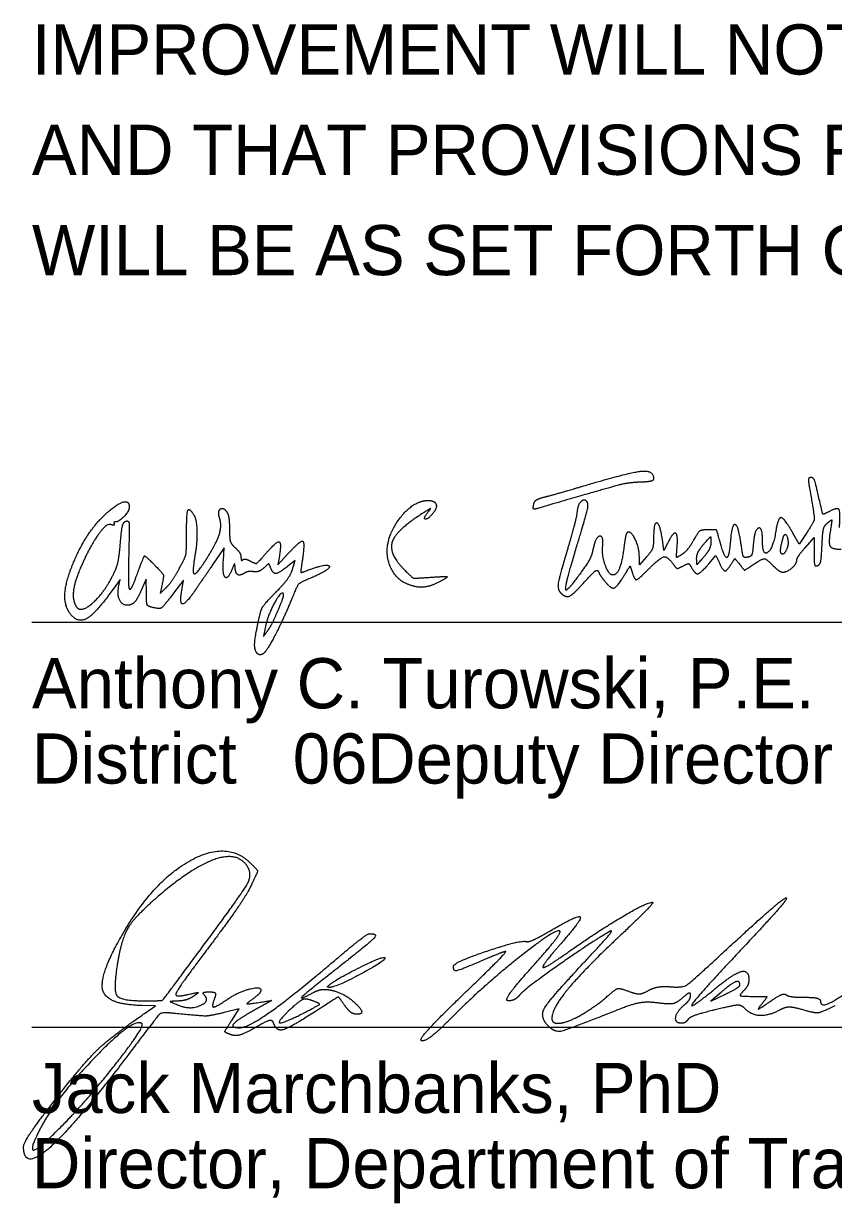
# Model space of a CAD drawing. Extents: x 0 to 34, y 0 to 22.
# Drawn here: x 24.504 to 26.766, y 7.305 to 10.597 of the extents above; entities that cross this region are included whole.
import ezdxf

# ---------------------------------------------------------------- set-up
doc = ezdxf.new("R2010")
doc.units = 0
doc.layers.add('GM_X_Minor_Lake', color=7, linetype='Continuous')
doc.layers.add('GM_X_Minor_Lake_Text', color=7, linetype='Continuous')

msp = doc.modelspace()

# ---------------------------------------------------------------- linework, layer by layer
at = {"layer": 'GM_X_Minor_Lake'}
for p, q in [((25.9287, 9.2547), (25.9287, 9.2547)), ((25.5689, 9.0363), (25.5689, 9.0363)), ((25.2156, 8.9606), (25.2156, 8.9606)), ((25.157, 8.8395), (25.157, 8.8395)), ((24.9902, 8.0019), (24.9902, 8.0019)), ((25.3555, 7.912), (25.3555, 7.912)), ((26.5045, 7.914), (26.5045, 7.914)), ((25.3107, 7.8703), (25.3107, 7.8703)), ((25.7273, 7.883), (25.7273, 7.883))]:
    msp.add_line(p, q, dxfattribs=at)
for points in [[(26.3033, 9.1485), (26.2923, 9.1263), (26.2879, 9.1577)], [(26.6905, 9.1753), (26.6698, 9.1442), (26.6524, 9.1752)], [(26.6875, 9.1355), (26.7115, 9.1629), (26.7115, 9.1219)], [(25.0623, 9.0989), (25.0648, 9.1343), (25.032, 9.0863)], [(25.2187, 9.112), (25.2144, 9.0863), (25.2425, 9.1171)], [(25.2556, 9.0747), (25.2625, 9.0987), (25.2419, 9.0825)], [(26.2437, 9.1088), (26.224, 9.0863), (26.2237, 9.1087)], [(26.4178, 9.0897), (26.4375, 9.1131), (26.4463, 9.0937)], [(24.7697, 9.0239), (24.774, 9.046), (24.757, 9.0221)], [(24.8473, 9.0092), (24.8471, 9.0463), (24.8322, 9.0135)], [(24.8914, 9.0326), (24.8859, 9.0063), (24.902, 9.0223)], [(24.946, 9.0149), (24.9507, 9.0436), (24.9233, 9.0077)], [(26.4527, 7.8943), (26.4232, 7.8687), (26.4638, 7.8884)], [(24.8425, 7.8349), (24.8732, 7.8561), (24.8354, 7.8568)], [(25.0855, 7.8151), (25.1067, 7.8474), (25.0649, 7.8373)]]:
    msp.add_lwpolyline(points, dxfattribs=at)
for points in [[(26.0677, 9.3068), (26.1931, 9.3442), (26.2635, 9.3515), (26.2635, 9.3274)], [(26.2635, 9.3274), (26.2635, 9.322), (26.2477, 9.3178), (26.2253, 9.3172)], [(26.7022, 9.3303), (26.6963, 9.3303), (26.6954, 9.3192), (26.6995, 9.2963)], [(26.7309, 9.2481), (26.7165, 9.3119), (26.7101, 9.3303), (26.7022, 9.3303)], [(26.2253, 9.3172), (26.1933, 9.3162), (26.1405, 9.3027), (25.9407, 9.2443)], [(25.9595, 9.2761), (25.9749, 9.2799), (26.0236, 9.2937), (26.0677, 9.3068)], [(26.6995, 9.2963), (26.7128, 9.2214), (26.7117, 9.2075), (26.6905, 9.1753)], [(24.7437, 9.2372), (24.7705, 9.2598), (24.7995, 9.2652), (24.7995, 9.2475)], [(25.5197, 9.124), (25.5201, 9.173), (25.5945, 9.2663), (25.6332, 9.2663)], [(25.6332, 9.2663), (25.6521, 9.2663), (25.6602, 9.2457), (25.6474, 9.2302)], [(25.9407, 9.2443), (25.9295, 9.2411), (25.9266, 9.2437), (25.9287, 9.2547)], [(25.9287, 9.2547), (25.9304, 9.2637), (25.9422, 9.2719), (25.9595, 9.2761)], [(26.039, 9.1045), (26.0736, 9.22), (26.0827, 9.2577), (26.0773, 9.2632)], [(26.0773, 9.2632), (26.0685, 9.2719), (26.0512, 9.2529), (26.0495, 9.2327)], [(24.6396, 9.0826), (24.6598, 9.1339), (24.7107, 9.2095), (24.7437, 9.2372)], [(24.7995, 9.2475), (24.7995, 9.2369), (24.7707, 9.2063), (24.7606, 9.2063)], [(24.9595, 9.1738), (24.9595, 9.2298), (24.9665, 9.2473), (24.9801, 9.2254)], [(24.9801, 9.2254), (24.9876, 9.2132), (24.9892, 9.1489), (24.983, 9.1129)], [(25.0516, 9.218), (25.0458, 9.2363), (25.0625, 9.2487), (25.0723, 9.2333)], [(25.0723, 9.2333), (25.0761, 9.2273), (25.0793, 9.2058), (25.0794, 9.1855)], [(25.6195, 9.2309), (25.5442, 9.1833), (25.5228, 9.1178), (25.5678, 9.0728)], [(25.6325, 9.2322), (25.6421, 9.2443), (25.6405, 9.2441), (25.6195, 9.2309)], [(25.6474, 9.2302), (25.6335, 9.2134), (25.6192, 9.2153), (25.6325, 9.2322)], [(26.0495, 9.2327), (26.0487, 9.2224), (26.0371, 9.1773), (26.0237, 9.1324)], [(26.7525, 9.2349), (26.7378, 9.227), (26.7353, 9.2285), (26.7309, 9.2481)], [(26.7823, 9.1906), (26.7857, 9.2343), (26.7766, 9.2478), (26.7525, 9.2349)], [(24.7485, 9.199), (24.7359, 9.2039), (24.6881, 9.1356), (24.6629, 9.077)], [(24.7574, 9.2006), (24.7584, 9.1975), (24.7544, 9.1968), (24.7485, 9.199)], [(24.7606, 9.2063), (24.7578, 9.2063), (24.7563, 9.2037), (24.7574, 9.2006)], [(24.775, 9.1497), (24.7778, 9.1849), (24.7833, 9.2063), (24.79, 9.2085)], [(24.79, 9.2085), (24.7983, 9.2113), (24.7999, 9.1922), (24.798, 9.1151)], [(25.015, 9.1028), (25.0431, 9.1472), (25.0586, 9.1959), (25.0516, 9.218)], [(26.2879, 9.1577), (26.2818, 9.2012), (26.2635, 9.2055), (26.2635, 9.1634)], [(26.5075, 9.1459), (26.5005, 9.1969), (26.4815, 9.2014), (26.4779, 9.1529)], [(26.5675, 9.1543), (26.5675, 9.1937), (26.5449, 9.1849), (26.5419, 9.1444)], [(26.6524, 9.1752), (26.629, 9.217), (26.6111, 9.2196), (26.605, 9.182)], [(26.7338, 9.1403), (26.7355, 9.1769), (26.7401, 9.1962), (26.7492, 9.2036)], [(26.7492, 9.2036), (26.7609, 9.2133), (26.7616, 9.2112), (26.7571, 9.1828)], [(24.9388, 9.0758), (24.9559, 9.1069), (24.9595, 9.1239), (24.9595, 9.1738)], [(25.0794, 9.1855), (25.0795, 9.1591), (25.084, 9.1447), (25.0955, 9.1343)], [(26.1212, 9.1366), (26.1245, 9.1685), (26.1015, 9.1648), (26.0949, 9.1325)], [(26.1924, 9.1783), (26.1887, 9.1783), (26.1837, 9.161), (26.1812, 9.1399)], [(26.2237, 9.1087), (26.2235, 9.1331), (26.2031, 9.1783), (26.1924, 9.1783)], [(26.2635, 9.1634), (26.2635, 9.1406), (26.2578, 9.1247), (26.2437, 9.1088)], [(26.3291, 9.1352), (26.332, 9.1713), (26.3181, 9.1785), (26.3033, 9.1485)], [(26.3747, 9.1546), (26.3657, 9.1386), (26.3512, 9.121), (26.3425, 9.1155)], [(26.4155, 9.1846), (26.3961, 9.184), (26.3878, 9.1779), (26.3747, 9.1546)], [(26.4032, 9.1439), (26.4221, 9.1653), (26.423, 9.1655), (26.4232, 9.1488)], [(26.4493, 9.1497), (26.4407, 9.1822), (26.4377, 9.1852), (26.4155, 9.1846)], [(26.605, 9.182), (26.5969, 9.1323), (26.5675, 9.1106), (26.5675, 9.1543)], [(26.6205, 9.1443), (26.6234, 9.1564), (26.6269, 9.1677), (26.6284, 9.1695)], [(26.6284, 9.1695), (26.634, 9.176), (26.641, 9.1458), (26.6366, 9.1343)], [(26.7571, 9.1828), (26.7513, 9.1467), (26.7608, 9.1303), (26.7876, 9.1303)], [(24.7618, 9.0743), (24.7666, 9.0853), (24.7725, 9.1192), (24.775, 9.1497)], [(25.0955, 9.1343), (25.1043, 9.1263), (25.1115, 9.1144), (25.1115, 9.1077)], [(25.1806, 9.1179), (25.2101, 9.152), (25.225, 9.1496), (25.2187, 9.112)], [(25.2425, 9.1171), (25.2773, 9.1553), (25.2902, 9.1499), (25.2828, 9.1003)], [(25.5689, 9.0363), (25.5476, 9.0466), (25.5194, 9.0968), (25.5197, 9.124)], [(26.0237, 9.1324), (25.9997, 9.0514), (25.9946, 9.0179), (26.0048, 9.0076)], [(26.0949, 9.1325), (26.092, 9.1183), (26.0839, 9.0985), (26.0769, 9.0885)], [(26.1498, 9.0583), (26.1386, 9.0583), (26.1187, 9.1127), (26.1212, 9.1366)], [(26.1812, 9.1399), (26.1762, 9.0979), (26.161, 9.0583), (26.1498, 9.0583)], [(26.3425, 9.1155), (26.3277, 9.1063), (26.3269, 9.1076), (26.3291, 9.1352)], [(26.3837, 9.1039), (26.3836, 9.1135), (26.3924, 9.1315), (26.4032, 9.1439)], [(26.4232, 9.1488), (26.4234, 9.1391), (26.4146, 9.1211), (26.4037, 9.1088)], [(26.4779, 9.1529), (26.4746, 9.1078), (26.461, 9.1063), (26.4493, 9.1497)], [(26.5263, 9.1079), (26.516, 9.106), (26.5119, 9.1143), (26.5075, 9.1459)], [(26.5419, 9.1444), (26.5402, 9.1205), (26.5356, 9.1097), (26.5263, 9.1079)], [(26.6366, 9.1343), (26.6283, 9.1127), (26.6149, 9.1211), (26.6205, 9.1443)], [(26.6635, 9.1005), (26.6635, 9.1047), (26.6743, 9.1205), (26.6875, 9.1355)], [(26.7115, 9.1219), (26.7115, 9.0927), (26.7144, 9.0819), (26.7215, 9.0843)], [(26.7215, 9.0843), (26.7278, 9.0864), (26.7324, 9.107), (26.7338, 9.1403)], [(24.798, 9.1151), (24.7966, 9.0619), (24.7979, 9.0183), (24.8008, 9.0183)], [(24.8201, 9.0563), (24.8401, 9.1107), (24.8441, 9.1128), (24.8721, 9.0841)], [(24.983, 9.1129), (24.9743, 9.0633), (24.9874, 9.0592), (25.015, 9.1028)], [(25.087, 9.0756), (25.0747, 9.045), (25.0596, 9.0592), (25.0623, 9.0989)], [(25.095, 9.0808), (25.0946, 9.0903), (25.0922, 9.0887), (25.087, 9.0756)], [(25.1115, 9.1077), (25.1115, 9.1011), (25.1138, 9.0979), (25.1165, 9.1007)], [(25.1165, 9.1007), (25.1193, 9.1035), (25.1291, 9.1017), (25.1382, 9.0969)], [(25.1382, 9.0969), (25.1526, 9.0892), (25.1582, 9.092), (25.1806, 9.1179)], [(25.1942, 9.0787), (25.19, 9.0897), (25.188, 9.0896), (25.1752, 9.078)], [(25.2828, 9.1003), (25.2779, 9.0678), (25.2788, 9.0643), (25.2911, 9.0691)], [(26.0769, 9.0885), (26.0249, 9.0138), (26.0132, 9.0187), (26.039, 9.1045)], [(26.2518, 9.077), (26.2818, 9.107), (26.3025, 9.1108), (26.318, 9.089)], [(26.318, 9.089), (26.3265, 9.077), (26.3315, 9.0759), (26.3451, 9.0832)], [(26.3451, 9.0832), (26.3585, 9.0904), (26.3633, 9.0896), (26.3691, 9.0792)], [(26.3691, 9.0792), (26.3798, 9.06), (26.3957, 9.0635), (26.4178, 9.0897)], [(26.4037, 9.1088), (26.3849, 9.0873), (26.384, 9.0871), (26.3837, 9.1039)], [(26.4463, 9.0937), (26.4569, 9.0704), (26.4681, 9.069), (26.4808, 9.0895)], [(26.4808, 9.0895), (26.49, 9.1042), (26.4907, 9.1042), (26.5039, 9.0879)], [(26.5039, 9.0879), (26.5173, 9.0712), (26.5176, 9.0712), (26.5405, 9.0865)], [(26.5405, 9.0865), (26.5671, 9.1042), (26.5784, 9.1034), (26.5999, 9.0819)], [(26.6249, 9.0663), (26.6366, 9.0663), (26.6635, 9.0901), (26.6635, 9.1005)], [(24.6342, 8.9507), (24.6185, 8.9722), (24.6211, 9.0357), (24.6396, 9.0826)], [(24.6629, 9.077), (24.6464, 9.0385), (24.6408, 8.9877), (24.6511, 8.9709)], [(24.6511, 8.9709), (24.6644, 8.9494), (24.7369, 9.0172), (24.7618, 9.0743)], [(24.8008, 9.0183), (24.8038, 9.0183), (24.8125, 9.0354), (24.8201, 9.0563)], [(24.8721, 9.0841), (24.8933, 9.0625), (24.8961, 9.055), (24.8914, 9.0326)], [(24.902, 9.0223), (24.9109, 9.0311), (24.9275, 9.0552), (24.9388, 9.0758)], [(25.032, 9.0863), (25.0139, 9.0599), (24.9911, 9.0267), (24.9813, 9.0126)], [(25.1215, 9.0636), (25.1084, 9.0554), (25.0956, 9.0637), (25.095, 9.0808)], [(25.1462, 9.0675), (25.1381, 9.0688), (25.127, 9.0671), (25.1215, 9.0636)], [(25.1752, 9.078), (25.1673, 9.0709), (25.1542, 9.0662), (25.1462, 9.0675)], [(25.2419, 9.0825), (25.2173, 9.0632), (25.2007, 9.0618), (25.1942, 9.0787)], [(25.2086, 9.0099), (25.2307, 9.0323), (25.2518, 9.0614), (25.2556, 9.0747)], [(25.2911, 9.0691), (25.3506, 9.0919), (25.365, 9.0749), (25.3071, 9.0501)], [(25.5678, 9.0728), (25.5906, 9.05), (25.5952, 9.0487), (25.6398, 9.0519)], [(26.0719, 9.0403), (26.0918, 9.0626), (26.1072, 9.0742), (26.1092, 9.0684)], [(26.1092, 9.0684), (26.1112, 9.063), (26.1191, 9.0507), (26.1269, 9.0411)], [(26.1269, 9.0411), (26.1444, 9.0194), (26.1621, 9.025), (26.1826, 9.0588)], [(26.1826, 9.0588), (26.197, 9.0824), (26.1982, 9.0829), (26.2032, 9.0671)], [(26.2032, 9.0671), (26.2106, 9.0439), (26.2208, 9.046), (26.2518, 9.077)], [(26.5999, 9.0819), (26.6085, 9.0733), (26.6197, 9.0663), (26.6249, 9.0663)], [(24.757, 9.0221), (24.7073, 8.9523), (24.6552, 8.922), (24.6342, 8.9507)], [(24.8052, 8.9761), (24.7863, 8.9688), (24.7648, 8.9979), (24.7697, 9.0239)], [(25.3071, 9.0501), (25.2757, 9.0367), (25.2684, 9.0288), (25.2535, 8.9924)], [(25.6639, 9.0385), (25.6366, 9.0244), (25.5956, 9.0235), (25.5689, 9.0363)], [(25.6398, 9.0519), (25.666, 9.0538), (25.6875, 9.0543), (25.6875, 9.053)], [(25.6875, 9.053), (25.6875, 9.0518), (25.6769, 9.0452), (25.6639, 9.0385)], [(26.0048, 9.0076), (26.0182, 8.9943), (26.0408, 9.0053), (26.0719, 9.0403)], [(24.8322, 9.0135), (24.8241, 8.9955), (24.8119, 8.9786), (24.8052, 8.9761)], [(24.8615, 8.9685), (24.8507, 8.9713), (24.8474, 8.9807), (24.8473, 9.0092)], [(24.9233, 9.0077), (24.894, 8.9694), (24.8837, 8.9628), (24.8615, 8.9685)], [(24.9813, 9.0126), (24.9565, 8.9769), (24.94, 8.9779), (24.946, 9.0149)], [(25.16, 8.9294), (25.1667, 8.9606), (25.1773, 8.9781), (25.2086, 9.0099)], [(25.2535, 8.9924), (25.2283, 8.9307), (25.1799, 8.8398), (25.1705, 8.8367)], [(25.2295, 9.0069), (25.2229, 9.0136), (25.1859, 8.9448), (25.1798, 8.9143)], [(25.2156, 8.9606), (25.2255, 8.9838), (25.2318, 9.0046), (25.2295, 9.0069)], [(25.1858, 8.9023), (25.1922, 8.9111), (25.2056, 8.9373), (25.2156, 8.9606)], [(25.157, 8.8395), (25.149, 8.8475), (25.1502, 8.8837), (25.16, 8.9294)], [(25.1798, 8.9143), (25.1745, 8.8884), (25.175, 8.8875), (25.1858, 8.9023)], [(25.1705, 8.8367), (25.1661, 8.8352), (25.16, 8.8364), (25.157, 8.8395)], [(24.7789, 8.0526), (24.8651, 8.203), (25.0732, 8.319), (25.1389, 8.2534)], [(25.1299, 8.2442), (25.104, 8.2862), (24.9779, 8.245), (24.8825, 8.1634)], [(24.9902, 8.0019), (25.1115, 8.1653), (25.144, 8.2215), (25.1299, 8.2442)], [(25.1389, 8.2534), (25.1577, 8.2346), (25.1577, 8.2295), (25.1394, 8.1911)], [(25.1394, 8.1911), (25.1284, 8.1681), (25.0767, 8.0926), (25.0245, 8.0232)], [(24.8825, 8.1634), (24.8159, 8.1064), (24.7771, 8.0423), (24.766, 7.971)], [(26.0326, 8.0111), (26.1131, 8.0677), (26.2445, 8.1449), (26.2602, 8.1449)], [(26.2602, 8.1449), (26.265, 8.1449), (26.2237, 8.1023), (26.1684, 8.0502)], [(26.4869, 8.0315), (26.5619, 8.1006), (26.6279, 8.1572), (26.6336, 8.1573)], [(26.6336, 8.1573), (26.6394, 8.1574), (26.5873, 8.0972), (26.518, 8.0236)], [(25.9736, 8.0646), (26.0524, 8.1108), (26.0646, 8.0975), (26.0054, 8.0302)], [(24.8354, 7.8568), (24.7375, 7.8585), (24.7141, 7.9396), (24.7789, 8.0526)], [(25.369, 7.9791), (25.4194, 8.022), (25.4649, 8.0571), (25.4701, 8.0573)], [(25.4701, 8.0573), (25.495, 8.0578), (25.4716, 8.0322), (25.3857, 7.9649)], [(25.7047, 7.9668), (25.7049, 7.9774), (25.8923, 8.0405), (25.908, 8.0354)], [(26.0017, 8.0644), (25.9921, 8.074), (25.7824, 7.907), (25.7045, 7.8278)], [(26.142, 8.0639), (26.0929, 8.0361), (25.9046, 7.9039), (25.8914, 7.888)], [(25.908, 8.0354), (25.9136, 8.0335), (25.9431, 8.0467), (25.9736, 8.0646)], [(25.9239, 7.964), (25.9702, 8.0157), (26.0052, 8.0609), (26.0017, 8.0644)], [(26.1684, 8.0502), (26.0687, 7.9565), (25.9795, 7.8484), (25.9795, 7.8214)], [(26.0768, 7.985), (26.123, 8.0342), (26.1523, 8.0697), (26.142, 8.0639)], [(24.844, 7.8699), (24.8907, 7.8699), (24.8953, 7.874), (24.9902, 8.0019)], [(25.0245, 8.0232), (24.9722, 7.9539), (24.9295, 7.8932), (24.9295, 7.8884)], [(25.7273, 7.883), (25.7983, 7.9514), (25.8537, 8.0074), (25.8502, 8.0074)], [(25.8502, 8.0074), (25.8468, 8.0074), (25.8178, 7.9962), (25.7857, 7.9824)], [(26.0054, 8.0302), (25.9774, 7.9984), (25.9545, 7.9687), (25.9545, 7.9643)], [(25.9545, 7.9643), (25.9545, 7.9598), (25.9896, 7.9809), (26.0326, 8.0111)], [(26.3119, 7.9091), (26.3453, 7.9063), (26.3688, 7.9227), (26.4869, 8.0315)], [(26.518, 8.0236), (26.3885, 7.8861), (26.3564, 7.8388), (26.4386, 7.9065)], [(24.766, 7.971), (24.7545, 7.8977), (24.776, 7.8699), (24.844, 7.8699)], [(25.1076, 7.7949), (25.1307, 7.7949), (25.2567, 7.8837), (25.369, 7.9791)], [(25.3555, 7.912), (25.3759, 7.9299), (25.5079, 7.9956), (25.5131, 7.9905)], [(25.5131, 7.9905), (25.5193, 7.9843), (25.3767, 7.9074), (25.359, 7.9074)], [(25.7857, 7.9824), (25.7231, 7.9556), (25.7044, 7.952), (25.7047, 7.9668)], [(25.9697, 7.7993), (25.9445, 7.8246), (25.9734, 7.8747), (26.0768, 7.985)], [(26.7295, 7.8684), (26.7295, 7.8456), (26.8248, 7.907), (26.8951, 7.9753)], [(25.3857, 7.9649), (25.2925, 7.8919), (25.271, 7.8704), (25.315, 7.8939)], [(25.8581, 7.8699), (25.8478, 7.8699), (25.8767, 7.9112), (25.9239, 7.964)], [(26.4386, 7.9065), (26.487, 7.9464), (26.5295, 7.9568), (26.5295, 7.9287)], [(25.0736, 7.8743), (25.1025, 7.8941), (25.167, 7.9116), (25.167, 7.8997)], [(25.359, 7.9074), (25.3542, 7.9074), (25.3526, 7.9095), (25.3555, 7.912)], [(26.137, 7.885), (26.1573, 7.903), (26.1701, 7.9056), (26.1939, 7.8966)], [(26.2489, 7.8987), (26.2623, 7.9062), (26.2906, 7.9109), (26.3119, 7.9091)], [(26.5045, 7.914), (26.5045, 7.9275), (26.4804, 7.9183), (26.4527, 7.8943)], [(26.4638, 7.8884), (26.4862, 7.8992), (26.5045, 7.9107), (26.5045, 7.914)], [(26.5295, 7.9287), (26.5295, 7.9198), (26.5227, 7.9057), (26.5145, 7.8974)], [(24.9357, 7.8693), (24.9133, 7.8685), (24.9138, 7.8671), (24.9399, 7.8567)], [(24.9295, 7.8884), (24.9295, 7.8836), (24.9449, 7.8833), (24.9638, 7.8877)], [(24.9795, 7.883), (24.9692, 7.876), (24.9495, 7.8699), (24.9357, 7.8693)], [(24.9399, 7.8567), (24.9698, 7.8447), (25.026, 7.8693), (25.0086, 7.8867)], [(24.9638, 7.8877), (24.9894, 7.8936), (24.9934, 7.8924), (24.9795, 7.883)], [(25.0086, 7.8867), (25.004, 7.8912), (25.0103, 7.8949), (25.0225, 7.8949)], [(25.0225, 7.8949), (25.037, 7.8949), (25.0422, 7.8885), (25.0375, 7.8762)], [(25.0375, 7.8762), (25.0285, 7.8529), (25.0414, 7.8523), (25.0736, 7.8743)], [(25.1453, 7.8756), (25.1264, 7.8618), (25.1284, 7.8605), (25.161, 7.8654)], [(25.167, 7.8997), (25.167, 7.8952), (25.1572, 7.8843), (25.1453, 7.8756)], [(25.161, 7.8654), (25.1977, 7.871), (25.1976, 7.8707), (25.1522, 7.8456)], [(25.3107, 7.8703), (25.2935, 7.8767), (25.277, 7.8716), (25.2576, 7.8538)], [(25.2826, 7.834), (25.329, 7.8577), (25.3325, 7.8623), (25.3107, 7.8703)], [(25.315, 7.8939), (25.3276, 7.9006), (25.3515, 7.9027), (25.3681, 7.8985)], [(25.4011, 7.8571), (25.3843, 7.8812), (25.3822, 7.8807), (25.3165, 7.8384)], [(25.3681, 7.8985), (25.4042, 7.8894), (25.4625, 7.8324), (25.4358, 7.8324)], [(25.617, 7.7581), (25.6067, 7.7583), (25.6563, 7.8145), (25.7273, 7.883)], [(25.8914, 7.888), (25.8831, 7.878), (25.8682, 7.8699), (25.8581, 7.8699)], [(25.9975, 7.8074), (26.0192, 7.8074), (26.1006, 7.8527), (26.137, 7.885)], [(26.1939, 7.8966), (26.2141, 7.8889), (26.2329, 7.8896), (26.2489, 7.8987)], [(26.3444, 7.8784), (26.3287, 7.8642), (26.3075, 7.8598), (26.2749, 7.864)], [(26.367, 7.8859), (26.367, 7.893), (26.3568, 7.8896), (26.3444, 7.8784)], [(26.3482, 7.8574), (26.3585, 7.866), (26.367, 7.8788), (26.367, 7.8859)], [(26.5145, 7.8974), (26.5028, 7.8858), (26.5087, 7.8824), (26.541, 7.8824)], [(26.541, 7.8824), (26.5785, 7.8824), (26.5809, 7.8804), (26.5654, 7.8611)], [(26.5871, 7.8669), (26.6085, 7.8819), (26.6293, 7.891), (26.6332, 7.8871)], [(26.6332, 7.8871), (26.6371, 7.8831), (26.6604, 7.8799), (26.6849, 7.8799)], [(26.6849, 7.8799), (26.7094, 7.8799), (26.7295, 7.8748), (26.7295, 7.8684)], [(24.9237, 7.835), (24.8903, 7.8383), (24.8786, 7.8278), (24.8019, 7.7262)], [(25.0649, 7.8373), (25.0246, 7.8276), (25.0023, 7.8272), (24.9237, 7.835)], [(25.1522, 7.8456), (25.1011, 7.8174), (25.0814, 7.7949), (25.1076, 7.7949)], [(25.3165, 7.8384), (25.2476, 7.794), (25.2101, 7.7843), (25.202, 7.8086)], [(25.2576, 7.8538), (25.2133, 7.8133), (25.2246, 7.8044), (25.2826, 7.834)], [(25.4358, 7.8324), (25.4262, 7.8324), (25.4106, 7.8435), (25.4011, 7.8571)], [(26.1693, 7.8468), (26.0233, 7.7891), (25.9882, 7.7808), (25.9697, 7.7993)], [(26.2749, 7.864), (26.2457, 7.8677), (26.2058, 7.8612), (26.1693, 7.8468)], [(26.3412, 7.8074), (26.3229, 7.8074), (26.3274, 7.8402), (26.3482, 7.8574)], [(26.4355, 7.8449), (26.3972, 7.8357), (26.3629, 7.8235), (26.3594, 7.8178)], [(26.5199, 7.847), (26.5088, 7.8582), (26.4887, 7.8577), (26.4355, 7.8449)], [(26.6162, 7.8445), (26.5854, 7.8281), (26.5376, 7.8293), (26.5199, 7.847)], [(26.5654, 7.8611), (26.5533, 7.8461), (26.5598, 7.8478), (26.5871, 7.8669)], [(26.6807, 7.8446), (26.6538, 7.8523), (26.6307, 7.8523), (26.6162, 7.8445)], [(26.7698, 7.8559), (26.7324, 7.8374), (26.7138, 7.8351), (26.6807, 7.8446)], [(24.8354, 7.8057), (24.8145, 7.8266), (24.596, 7.6009), (24.5497, 7.5106)], [(24.5916, 7.5927), (24.6692, 7.6932), (24.7493, 7.7705), (24.8425, 7.8349)], [(24.6198, 7.5293), (24.6874, 7.5984), (24.8431, 7.798), (24.8354, 7.8057)], [(25.0843, 7.775), (25.0661, 7.782), (25.0662, 7.7856), (25.0855, 7.8151)], [(25.202, 7.8086), (25.1991, 7.8172), (25.1799, 7.812), (25.1508, 7.7948)], [(25.7045, 7.8278), (25.6667, 7.7893), (25.6273, 7.7579), (25.617, 7.7581)], [(25.9795, 7.8214), (25.9795, 7.8137), (25.9876, 7.8074), (25.9975, 7.8074)], [(26.3594, 7.8178), (26.3559, 7.8121), (26.3477, 7.8074), (26.3412, 7.8074)], [(25.1508, 7.7948), (25.1252, 7.7797), (25.0953, 7.7708), (25.0843, 7.775)], [(24.8019, 7.7262), (24.6496, 7.5241), (24.5045, 7.3955), (24.5045, 7.4625)], [(24.5045, 7.4625), (24.5045, 7.4721), (24.5437, 7.5307), (24.5916, 7.5927)], [(24.5497, 7.5106), (24.5184, 7.4496), (24.55, 7.4581), (24.6198, 7.5293)]]:
    msp.add_open_spline(points, degree=2, dxfattribs=at)
at = {"layer": 'GM_X_Minor_Lake_Text'}
for p, q in [((24.5279, 8.9262), (28.0279, 8.9262)), ((24.5279, 7.7968), (28.0279, 7.7968))]:
    msp.add_line(p, q, dxfattribs=at)

# ---------------------------------------------------------------- texts
at = {"layer": 'GM_X_Minor_Lake'}
for s, p in [('Anthony C. Turowski, P.E.', (24.5279, 8.6862)), ('District       Deputy Director', (24.5279, 8.4762)), ('              06', (24.5279, 8.4762)), ('Jack Marchbanks, PhD', (24.5279, 7.5568)), ('Director, Department of Transportation', (24.5279, 7.3468))]:
    msp.add_text(s, height=0.14, dxfattribs=at).set_placement(p)
at = {"layer": 'GM_X_Minor_Lake_Text'}
for s, p in [('IMPROVEMENT WILL NOT REQUIRE THE CLOSING TO TRAFFIC OF THE HIGHWAY', (24.5279, 10.455)), ('AND THAT PROVISIONS FOR THE MAINTENANCE AND SAFETY OF TRAFFIC', (24.5279, 10.175)), ('WILL BE AS SET FORTH ON THE PLANS AND ESTIMATES.', (24.5279, 9.895))]:
    msp.add_text(s, height=0.14, dxfattribs=at).set_placement(p)

doc.saveas('drawing.dxf')
